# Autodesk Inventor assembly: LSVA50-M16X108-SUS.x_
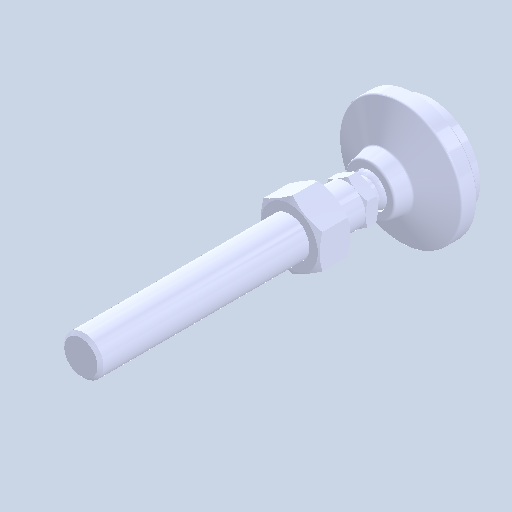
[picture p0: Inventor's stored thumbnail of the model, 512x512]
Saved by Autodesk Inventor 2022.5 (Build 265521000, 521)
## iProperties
Created: 2024-08
Part Number: LSVA50-M16X108-SUS.x_
Document SubType Name: Assembly
Designer: ImaoCorp
Author: ImaoCorp
Sending System: SOLIDWORKS 2022-2022290
MC: AMD64
MC_MODEL: Intel64 Family 6 Model 60 Stepping 3, GenuineIntel
OS: Windows_NT
FRU: Parasolid Version 33.1, build 260,  4-25-2022
FORMAT: text
GUISE: transmit
KEY: FILELSVA50-M16X108-SUS.x_t
DATE: Fri Aug 23 16:08:33 2024
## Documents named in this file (4)
- X:\14_SW2022-Inv2022\06_2024-10新製品(SME)\ELS_データ\l\lsva50-m16x108-sus\LSVA50-M16X108-SUS.x_.iam
- X:\14_SW2022-Inv2022\06_2024-10新製品(SME)\ELS_データ\l\lsva50-m16x108-sus\LSVA50-M16X108-SUS_01.ipt
- X:\14_SW2022-Inv2022\06_2024-10新製品(SME)\ELS_データ\l\lsva50-m16x108-sus\LSVA50-M16X108-SUS_02.ipt
- X:\14_SW2022-Inv2022\06_2024-10新製品(SME)\ELS_データ\l\lsva50-m16x108-sus\LSVA50-M16X108-SUS_03.ipt
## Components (3 placed, 3 different names)
1. LSVA50-M16X108-SUS_01
2. LSVA50-M16X108-SUS_02
3. LSVA50-M16X108-SUS_03
